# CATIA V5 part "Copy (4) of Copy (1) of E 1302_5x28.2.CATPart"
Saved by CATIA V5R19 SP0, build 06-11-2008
Part number: Copy (4) of Copy (1) of E 1302_5x28.2
Nomenclature: E 1302_5x28
Source: Unknown
Description: PART-E 1302_5x28-DESC
Bounding box of the stored display mesh (mm): x -2.5 to 2.5, y -2.5 to 2.5, z 0 to 28
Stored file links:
  C:\Users\jsmid\Desktop\DP_Smidak_Forma LEGO\Copy (4) of Copy (1) of E 1302_5x28.2.CATPart
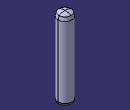
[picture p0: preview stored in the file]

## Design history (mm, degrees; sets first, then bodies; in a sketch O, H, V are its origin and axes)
Body1 "E 1302_5x28" (main body)
  Solid1: solid without history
